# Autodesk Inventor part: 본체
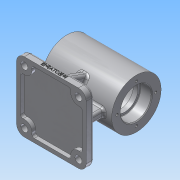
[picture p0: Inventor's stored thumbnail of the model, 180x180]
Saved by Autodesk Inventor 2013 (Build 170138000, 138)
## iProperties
Created: 2019-06
Part Number: 본체
Material: 알루미늄 6061
Document SubType Name: Modeling
Designer: Administrator
Density: 2.71 g/cm^3
Mass: 612.634 g
Surface Area: 622.716 cm^2
Volume: 226.064 cm^3
Author: Administrator
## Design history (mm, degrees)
sketch "스케치1"
  geometry: L1 (-45, 32)-(-45, 20); L2 (-45, 20)-(-30, 20); L3 (-30, 20)-(-30, 17); L4 (-30, 17)-(-24, 17); L5 (-24, 17)-(-24, 25); L6 (-24, 25)-(24, 25); L7 (24, 25)-(24, 17); L8 (24, 17)-(30, 17); L9 (30, 17)-(30, 20); L10 (30, 20)-(45, 20); L11 (45, 20)-(45, 32); L12 (45, 32)-(-45, 32); L13 (-45, 0)-(45, 0); 2 further points
  constraints: 26 end point, 4 vertical, 2 point on line, 1 coincident, 1 horizontal, 1 midpoint
  dimensions: "d0" = 90 distance of L13.start L13.end; "d3" = 34 diameter of L4 L13; "d4" = 34 diameter of L8 L13; "d5" = 50 diameter of L6 L13; "d6" = 40 diameter of L2 L13; "d7" = 40 diameter of L10 L13; "d8" = 64 diameter of L12 L13; "d9" = 15 distance of L1.end L2.end; "d10" = 48 distance of L5.end L6.end; "d11" = 90 distance of L11.end L1.start; "d12" = 15 distance of L9.end L10.end; "d13" = 6 distance of L3.end L4.end; "d14" = 6 distance of L7.end L8.end
revolve "회전1" sketch "스케치1" stored, may be unused: angle "d15" = 90 deg
node "작업 평면1"
sketch "스케치2"
  geometry: L1 (45, -45)-(-45, -45); L2 (-45, -45)-(-45, 45); L3 (-45, 45)-(45, 45); L4 (45, 45)-(45, -45); L5 (45, -45)-(-45, 45); L6 (-45, -45)-(45, 45); 3 further points
  constraints: 12 end point, 3 midpoint, 2 parallel, 1 coincident, 1 horizontal, 1 perpendicular
  dimensions: "d17" = 90 distance of L2.end L3.end; "d18" = 90 distance of L1.end L2.end
extrude "돌출1" join sketch "스케치2" distance "d19" = 10; taper "d20" = 0 deg
sketch "스케치3"
  geometry: L1 (45, 45)-(45, -45) reference; L2 (-35, 5)-(35, 5); L3 (35, 5)-(35, -5); L4 (35, -5)-(-35, -5); L5 (-35, -5)-(-35, 5); 2 further points
  constraints: 8 end point, 2 parallel, 1 horizontal, 1 horizontal alignment, 1 midpoint, 1 perpendicular
  dimensions: "d28" = 70 distance of L2.start L2.end; "d30" = 10 distance of L2.end L3.end; "d31" = 10 distance between parallel lines of L1 L3
extrude "돌출2" join sketch "스케치3" stored distance "d32" = 10; taper "d33" = 0 deg
sketch "스케치4"
  geometry: L1 (-22.189, -23.058)-(-55, -35); L2 (-55, -45)-(-55, 45) reference; L3 (-65, -45)-(-55, -45) reference; 2 further points
  constraints: 2 end point, 1 point on line, 2 other
  dimensions: "d34" = 10 distance from line of L1.end L3; "d35" = 110 deg angle of L1 L2
feature "리브1" sketch "스케치4" dims "d36" = 1, "d37" = 10, "d38" = 0, "d39" = 0, "d40" = 1, "d41" = 1
node "작업 평면2"
sketch "스케치5"
  geometry: C1 r 5 at (0, 0); 1 further point
  constraints: 1 centre point, 1 coincident
  dimensions: "d43" = 10 diameter of C1
extrude "돌출3" join sketch "스케치5" stored distance "d44" = 10; taper "d45" = 0 deg
hole "구멍1" diameter "d48" = 4.917; stored, may be unused: countersink angle "d52" = 90 deg, drill point angle "d54" = 118 deg; dims "d46" = 10, "d47" = 10, "d49" = 6, "d50" = 4, "d51" = 2, "d53" = 8
sketch "스케치6"
  geometry: 2 further points
  constraints: 1 vertical alignment
  dimensions: "d55" = 25 distance of point (0, 25) point (0, 0)
hole "구멍2" sketch "스케치6" at (0, 25) diameter "d56" = 3.242; stored, may be unused: countersink angle "d60" = 90 deg, drill point angle "d62" = 118 deg; dims "d57" = 7, "d58" = 4, "d59" = 2, "d61" = 9
fillet "모깎기1" dims "d66" = 10
hole "구멍3" diameter "d69" = 9; stored, may be unused: countersink angle "d73" = 90 deg, drill point angle "d75" = 118 deg; dims "d67" = 10, "d68" = 10, "d70" = 7, "d71" = 4, "d72" = 2, "d74" = 9
sketch "스케치7"
  geometry: L1 (-26.34, 40)-(26.34, 40); L2 (-40, 26.34)-(-40, 0); L3 (-40, 0)-(40, 0); L4 (40, 0)-(40, 26.34); L5 (-26.34, -40)-(26.34, -40); L6 (-40, -26.34)-(-40, 0); L7 (40, 0)-(40, -26.34); C1 r 4.5 at (-35, 35) reference; C2 r 4.5 at (35, 35) reference; C3 r 4.5 at (-35, -35); C4 r 4.5 at (35, -35); A1 r 10 centre (-35, 35) between (-40, 26.34) and (-26.34, 40); A2 r 10 centre (35, 35) between (26.34, 40) and (40, 26.34); A3 r 10 centre (-35, -35) between (-26.34, -40) and (-40, -26.34); A4 r 10 centre (35, -35) between (40, -26.34) and (26.34, -40); 1 further point
  constraints: 14 end point, 8 point on circle, 8 symmetric about line, 6 centre point, 4 coincident, 2 vertical, 1 horizontal, 1 midpoint, 4 other
  dimensions: "d76" = 10 radius of A1; "d77" = 10 radius of A2; "d78" = 40 distance from line of point (0, 0) L1; "d79" = 52.67949 distance of L1.start L1.end; "d80" = 40 distance from line of point (0, 0) L2; "d81" = 40 distance from line of point (0, 0) L4
extrude "돌출4" cut sketch "스케치7" distance "d82" = 5; taper "d83" = 0 deg
fillet "모깎기2" dims "d84" = 3
fillet "모깎기3" dims "d85" = 3
fillet "모깎기4" dims "d86" = 3, "d87" = 0.6
chamfer "모따기1" distance "d88" = 1; stored, may be unused: second distance "d89" = 2, angle "d90" = 45 deg
fillet "모깎기5" dims "d91" = 2
sketch "스케치8"
  geometry: L1 (-10, 7)-(-10, 0) reference; L2 (70, 0)-(0, 0) reference; 2 further points
  constraints: 1 other
  dimensions: "d92" = 45 distance from line of L1 point (35, 4); "d96" = 4 distance from line of point (35, 4) L2
feature "엠보싱1" sketch "스케치8" dims "d0" = 90, "d3" = 34, "d4" = 34, "d5" = 50, "d6" = 40, "d7" = 40, "d8" = 64, "d9" = 15, "d10" = 48, "d11" = 90, "d12" = 15, "d13" = 6, "d14" = 6, "d17" = 90, "d18" = 90, "d94" = 0.5, "d95" = 0
node "솔리드1"
mirror "대칭1"
pattern_circular "원형 패턴1" dims angle "d64" = 360 deg
mirror "대칭2"
mirror "대칭3"
mirror "대칭4"
other parameters: "d16" = -65, "d42" = 35
